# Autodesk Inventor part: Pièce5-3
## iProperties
Created: 2009-06
Part Number: Pièce5-3
Document SubType Name: Modeling
Designer: ajtco
Manufacturer: Standard
Standards Organization: Custom
Author: ajtco
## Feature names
1. Extrusion1
